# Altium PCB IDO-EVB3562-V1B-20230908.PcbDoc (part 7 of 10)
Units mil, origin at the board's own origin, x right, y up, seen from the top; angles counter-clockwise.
Board outline 5314.96 x 3543.31 mil, 4 copper layers (TOP, L2-VCC, L3-GND, BOTTOM), stack 28.8 mil thick; 747 components, 560 nets, 2514 pads, 1964 vias.
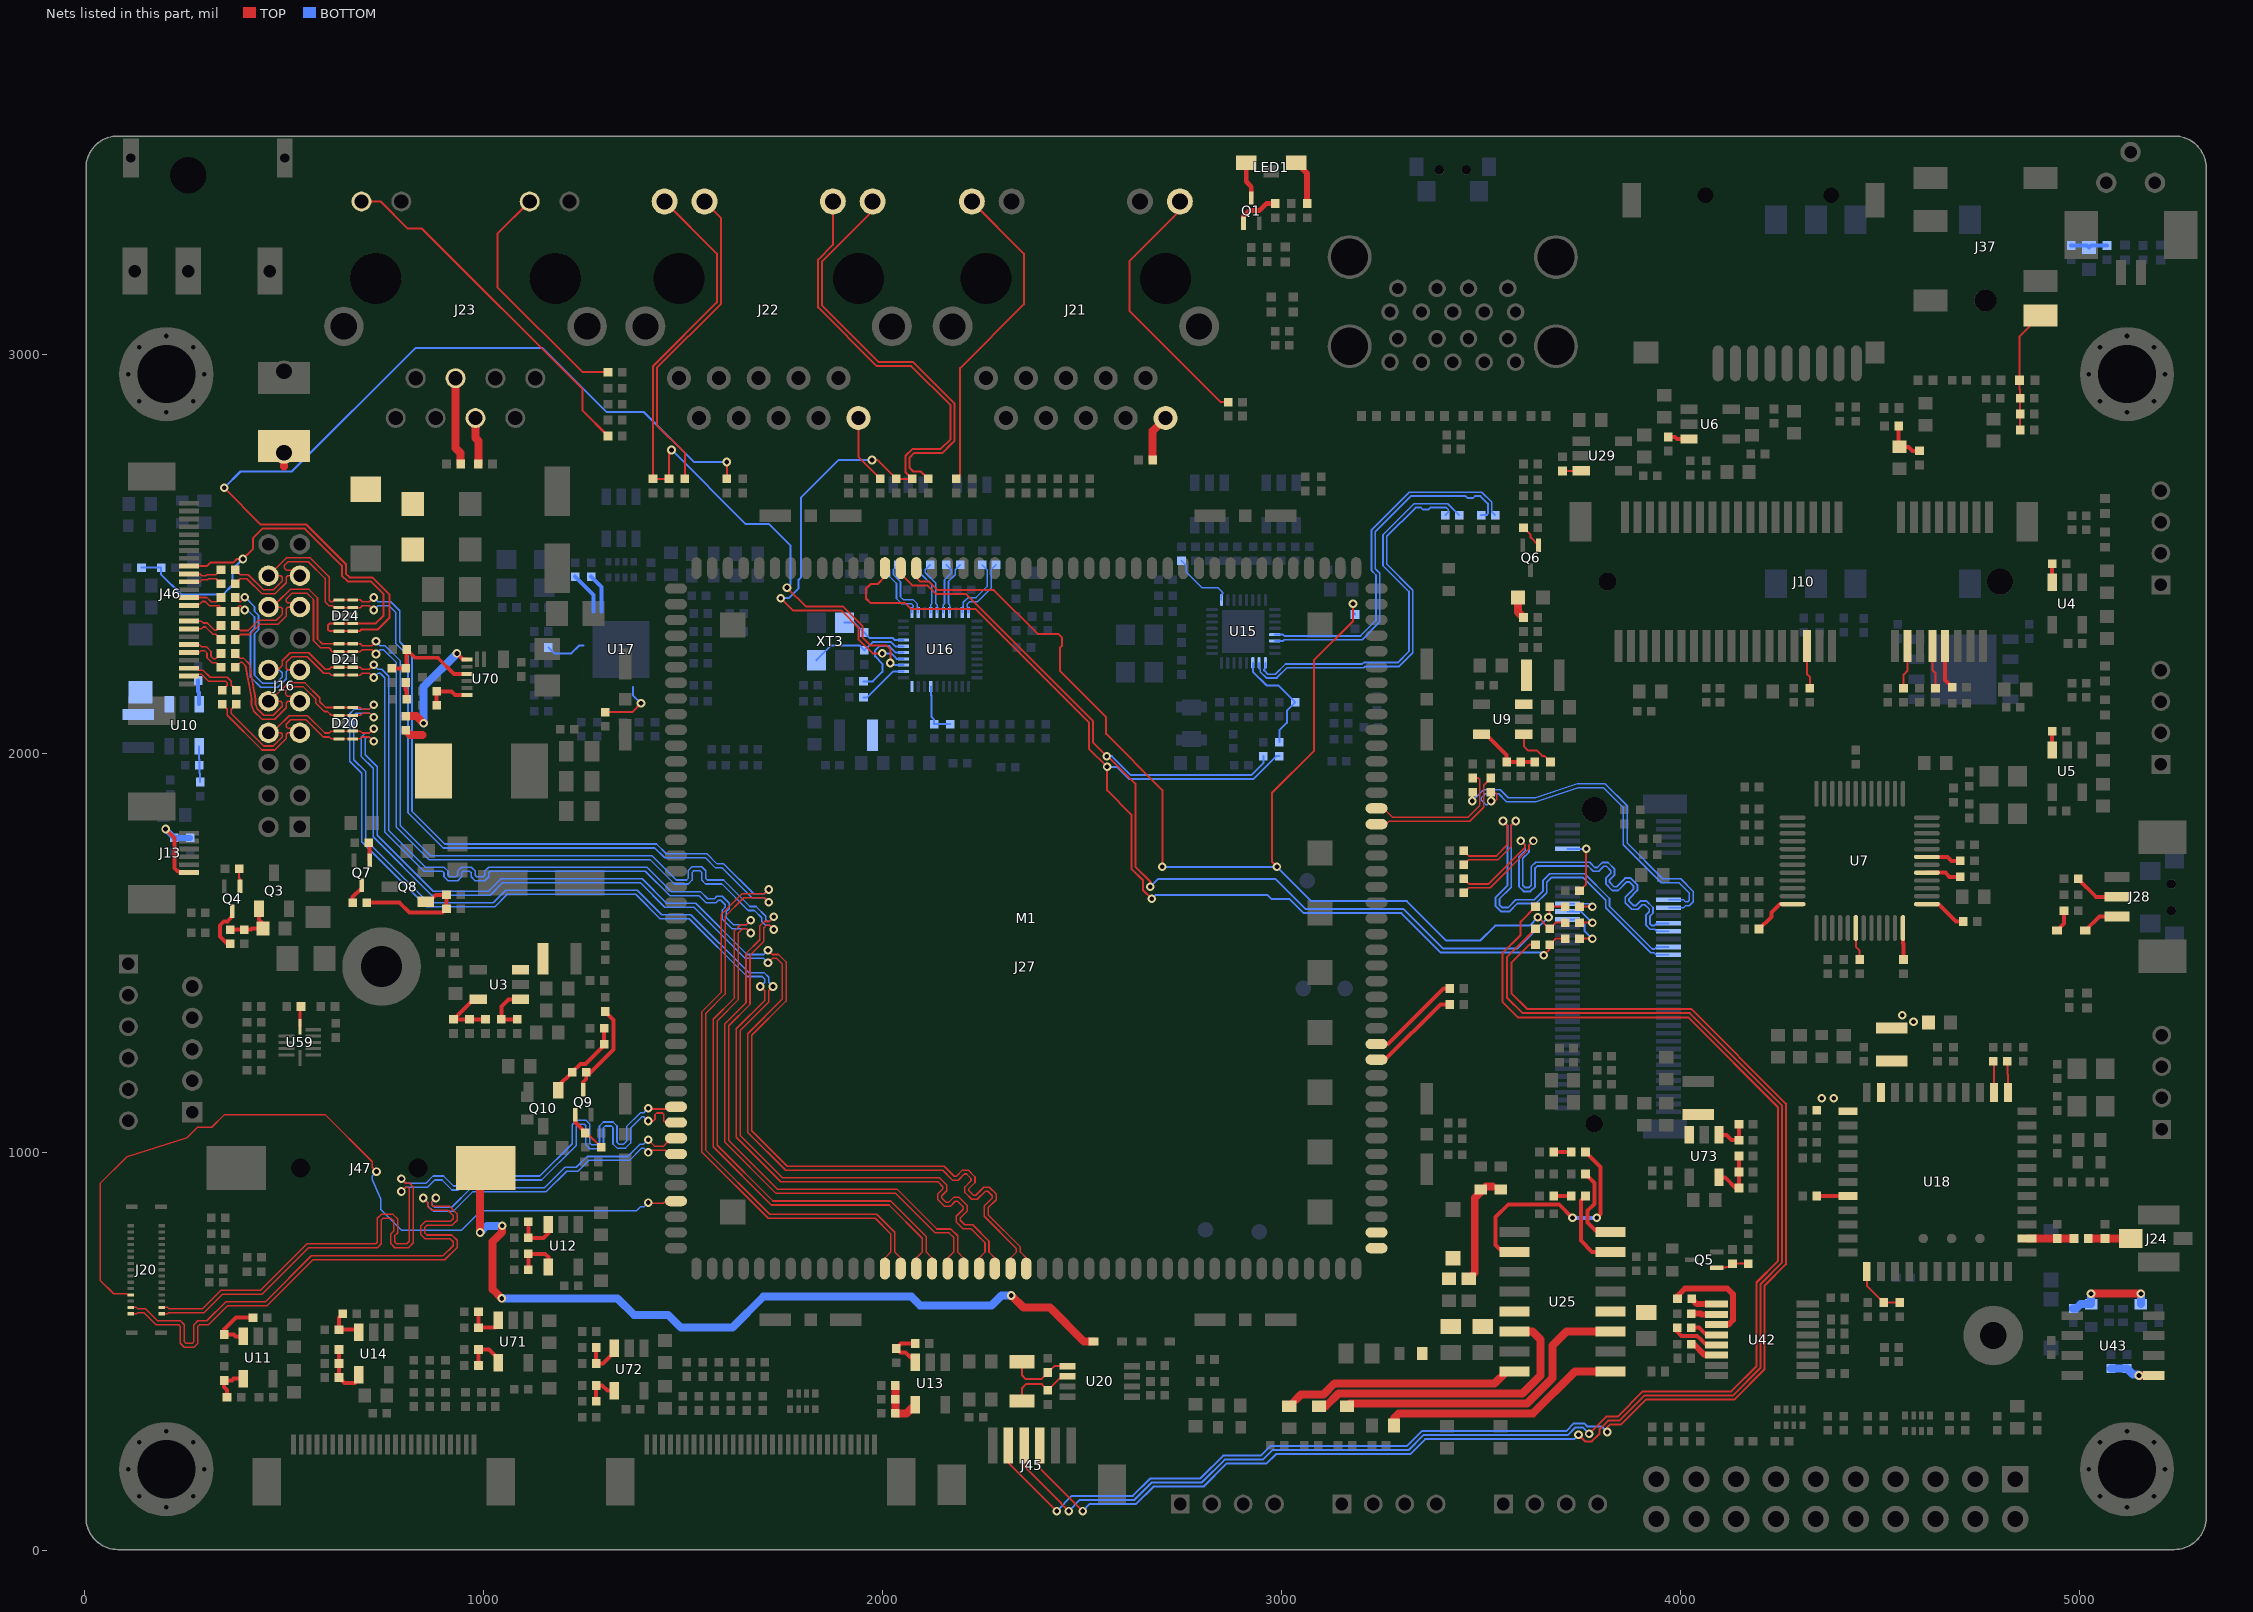
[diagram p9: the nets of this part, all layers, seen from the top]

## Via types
v1: diameter 21.65, hole 11.81, TOP to BOTTOM, 1964 vias

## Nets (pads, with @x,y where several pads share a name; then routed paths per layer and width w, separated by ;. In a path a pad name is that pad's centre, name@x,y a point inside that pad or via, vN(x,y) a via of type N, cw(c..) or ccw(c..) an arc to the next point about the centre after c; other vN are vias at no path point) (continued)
MIPI_CSI_RX1_D1P: J20.7 M1.126 | length 2051.3
  TOP w4: J20.7@116.03,642 108,642 105.12,644.88 72.98,644.88 39,678.86 39,921.14 106.22,988.37 256.79,1035.94 283.03,1062.17 318.8,1062.17 350.63,1094 603,1094 721.2,975.8 721.2,961.88 v1(732.03,951.05) ; v1(1413,873.31) 1414.31,872 1451.01,872 1456.17,877.16 M1.126@1482.87,877.16
  BOTTOM w4: v1(732.03,951.05) 721.2,940.23 721.2,931.01 742.52,882.01 742.52,856.25 794.77,804 944.9,804 993.9,853 1383.86,853 1393.34,862.48 1402.17,862.48 v1(1413,873.31)
MIPI_CSI_RX1_D2N: J20.3 M1.123 | length 2039.2
  TOP w4: J20.3@116.03,610.51 130.13,610.51 133,607.63 152.51,607.63 183.14,577 240.39,577 250.25,567.14 250.25,525 254.25,521 270.25,521 274.25,525 274.25,567.14 284.11,577 306.49,577 354.44,624.96 453.5,624.96 568.54,740 898.86,740 924,765.14 924,774.86 916.65,782.21 854.2,782.21 843.35,793.06 843.35,815.35 854.2,826.21 917.06,826.21 924,833.14 924,840.86 910.86,854 870,854 860,864 860,874.17 v1(849.17,885) ; v1(1413,999.13) 1418.87,1005 1456,1005 1465.72,995.28 M1.123@1482.87,995.28
  BOTTOM w4: v1(849.17,885) 860,874.17 860,865.86 873.86,852 925.01,852 974.01,901 1157.61,901 1208.79,952.17 1237.13,952.17 1263.96,979 1366.14,979 1397.1,1009.96 1402.17,1009.96 v1(1413,999.13)
MIPI_CSI_RX1_D2P: J20.1 M1.122 | length 2049.7
  TOP w4: J20.1@116.03,594.76 130.13,594.76 133,597.63 148.37,597.63 179,567 236.25,567 240.25,563 240.25,520.86 250.11,511 274.39,511 284.25,520.86 284.25,563 288.25,567 310.63,567 358.58,614.96 457.64,614.96 572.68,730 903,730 934,761 934,779 920.79,792.21 858.35,792.21 853.35,797.21 853.35,811.21 858.35,816.21 921.21,816.21 934,829 934,845 915,864 874.14,864 870,868.14 870,874.17 v1(880.83,885) ; v1(1413,1030.79) 1428.79,1015 1452,1015 1459,1022 1459,1026 1467.64,1034.65 M1.122@1482.87,1034.65
  BOTTOM w4: v1(880.83,885) 870,874.17 870,870 878,862 920.87,862 969.87,911 1153.47,911 1204.64,962.17 1232.99,962.17 1259.82,989 1362,989 1392.96,1019.96 1402.17,1019.96 v1(1413,1030.79)
MIPI_CSI_RX1_D3N: J20.4 M1.121 | length 2040.2
  TOP w4: J20.4@193.98,610.51 208.08,610.51 210.95,607.63 296.11,607.63 342.43,653.96 441.48,653.96 557.53,770 730.06,770 734.06,774 734.06,833.8 743.92,843.66 773.34,843.66 785,832 785,798 778.06,791.06 778.06,774 782.06,770 807.86,770 814.35,776.49 814.35,908.54 810.83,912.05 805.17,912.05 v1(794.35,901.23) ; v1(1413,1077.87) 1425.87,1077.87 1430,1082 1430,1094 1434,1098 1449,1098 1452,1095 1452,1078 1455.98,1074.02 M1.121@1482.87,1074.02
  BOTTOM w4: v1(794.35,901.23) 805.17,912.05 859.91,912.05 877.86,930 896,930 921,905 937,905 962,930 1145.6,930 1232.32,1016.72 1232.32,1064.01 1237.99,1069.67 1252.85,1069.67 1256.85,1065.67 1256.85,1017.86 1266.7,1008 1290.99,1008 1300.85,1017.86 1300.85,1061.44 1304.85,1065.44 1320.85,1065.44 1324.85,1061.44 1324.85,1020.15 1335,1010 1356.13,1010 1368.85,1022.72 1368.85,1059.85 1397.7,1088.7 1402.17,1088.7 v1(1413,1077.87)
MIPI_CSI_RX1_D3P: J20.2 M1.120 | length 2040.9
  TOP w4: J20.2@193.98,594.76 208.08,594.76 210.95,597.63 300.25,597.63 346.57,643.96 445.62,643.96 561.67,760 734.2,760 744.06,769.86 744.06,829.66 748.06,833.66 769.2,833.66 775,827.86 775,802.14 768.06,795.2 768.06,769.86 777.92,760 812,760 824.35,772.35 824.35,912.68 814.97,922.05 805.17,922.05 v1(794.35,932.88) ; v1(1413,1109.53) 1414.53,1108 1458,1108 1463.39,1113.39 M1.120@1482.87,1113.39
  BOTTOM w4: v1(794.35,932.88) 805.17,922.05 855.77,922.05 873.72,940 900.14,940 925.14,915 932.86,915 957.86,940 1141.46,940 1222.32,1020.87 1222.32,1068.15 1233.85,1079.67 1256.99,1079.67 1266.85,1069.82 1266.85,1022 1270.85,1018 1286.85,1018 1290.85,1022 1290.85,1065.58 1300.7,1075.44 1324.99,1075.44 1334.85,1065.58 1334.85,1024.3 1339.14,1020 1351.99,1020 1358.85,1026.86 1358.85,1063.99 1393.56,1098.7 1402.17,1098.7 v1(1413,1109.53)
MIPI_DSI_RST: C93.2 D24.4 D24.5 D24.6 D24.7 J46.16 R78.1 R444.1 | length 3524.9
  TOP w5: J46.16@262.01,2468.9 306.9,2468.9 316.35,2478.35 373.67,2478.35 382,2486.68 v1(397,2486.68) 422,2511.68 422,2539 445.75,2562.75 552.25,2562.75 645,2470 645,2445 659.52,2430.48 717.62,2430.48 750,2398.11 750,2345 730.32,2325.32 D24.7@672.22,2325.32 D24.4@637.78,2325.32 615.32,2325.32 610,2320 610,2310 614.37,2305.63 D24.5@637.78,2305.63 D24.6@672.22,2305.63 690,2305.63 694.37,2310 735,2310 765,2340 765,2397.25 721.77,2440.48 664.52,2440.48 655,2450 655,2474.14 556.39,2572.75 442.25,2572.75 v1(350,2665) ; R78.1@1610,2687.72 v1(1610,2730)
  BOTTOM w5: C93.2@142.72,2465 R444.1@192.28,2465 192.28,2447.72 241.78,2398.22 347.73,2398.22 371,2421.49 371,2460.68 v1(397,2486.68) ; v1(350,2665) 391,2706 520,2706 829.5,3015.5 1148.55,3015.5 1309.05,2855 1402.54,2855 1527.54,2730 v1(1610,2730)
MIPI_DSI_TX_CLKN/LVDS_TX_CLKN: D21.4 D21.7 J16.15 M1.147 R1186.1 | length 3564.1
  TOP w4: R1186.1@377.72,2285 390.22,2297.5 414.64,2297.5 440.14,2323 476.68,2323 476.71,2322.96 485,2322.96 505.63,2343.59 505.63,2362.18 509.63,2366.18 J16.15@540,2366.18 529.18,2377 509,2377 505.63,2380.37 505.63,2386.32 519.71,2400.39 558.61,2400.39 574,2385 574,2281.86 591.49,2264.37 613.25,2264.37 617.25,2260.37 617.25,2257.76 620.32,2254.68 D21.7@637.78,2254.68 D21.4@672.22,2254.68 691.43,2254.68 696.28,2259.53 719.94,2259.53 v1(730.76,2248.7) ; v1(1727.83,1557.96) 1717.71,1568.08 1708.5,1568.08 1702.83,1562.4 1702.83,1528.04 1668.18,1493.4 1668.18,1370.18 1614.82,1316.82 1614.82,1029.24 1737.67,906.39 2037.75,906.39 2136.89,807.25 2171.39,807.25 2188.66,789.98 2188.66,749.26 2203.35,734.58 M1.147@2203.35,707.87
  BOTTOM w4: v1(730.76,2248.7) 741.59,2259.53 749.33,2259.53 781.83,2227.03 781.83,1814.19 862.84,1733.17 1417.7,1733.17 1478.87,1672 1513.14,1672 1522.99,1681.86 1522.99,1701 1526.99,1705 1542.99,1705 1546.99,1701 1546.99,1681.86 1556.85,1672 1597.75,1672 1664.09,1605.65 1679.35,1605.65 1697.83,1587.17 1697.83,1578.16 1707.2,1568.79 1717,1568.79 v1(1727.83,1557.96)
MIPI_DSI_TX_CLKP/LVDS_TX_CLKP: D21.5 D21.6 J16.16 M1.146 R1187.1 | length 3569.8
  TOP w4: R1187.1@377.72,2320 390.22,2307.5 410.5,2307.5 436,2333 480.82,2333 480.86,2332.96 495.63,2347.73 495.63,2362.18 491.63,2366.18 J16.16@461.26,2366.18 473.08,2378 483.17,2378 515.57,2410.39 562.75,2410.39 584,2389.14 584,2286 595.63,2274.37 D21.6@637.78,2274.37 D21.5@672.22,2274.37 691.44,2274.37 696.28,2269.53 719.94,2269.53 v1(730.76,2280.35) ; v1(1727.83,1589.61) 1716.29,1578.08 1704.36,1578.08 1692.83,1566.55 1692.83,1532.18 1658.18,1497.54 1658.18,1374.33 1604.82,1320.96 1604.82,1025.1 1733.53,896.39 2033.61,896.39 2132.75,797.25 2167.25,797.25 2178.66,785.84 2178.66,749.26 2163.98,734.58 M1.146@2163.98,707.87
  BOTTOM w4: v1(730.76,2280.35) 741.59,2269.53 753.48,2269.53 791.83,2231.17 791.83,1818.33 866.98,1743.17 1421.84,1743.17 1483.01,1682 1508.99,1682 1512.99,1686 1512.99,1705.14 1522.85,1715 1547.14,1715 1556.99,1705.14 1556.99,1686 1560.99,1682 1601.89,1682 1668.24,1615.65 1683.49,1615.65 1707.83,1591.31 1707.83,1582.3 1711.35,1578.79 1717,1578.79 v1(1727.83,1589.61)
MIPI_DSI_TX_D0N/LVDS_TX_D0N: D20.1 D20.10 J16.7 M1.151 R1182.1 | length 3487.9
  TOP w4: R1182.1@345,2122.28 357.5,2109.78 357.5,2095.36 444.86,2008 477.14,2008 505.63,2036.49 505.63,2047.22 509.63,2051.22 J16.7@540,2051.22 529.22,2062 510,2062 505.63,2066.37 505.63,2072.47 517.16,2084 555,2084 598.52,2040.47 613.72,2040.47 618.57,2035.63 D20.10@637.78,2035.63 D20.1@672.22,2035.63 691.43,2035.63 696.28,2040.47 713.94,2040.47 v1(724.76,2029.65) ; v1(1713.27,1506.2) 1724.1,1495.37 1739.63,1495.37 1758.65,1476.35 1758.65,1378.62 1672.82,1292.79 1672.82,1053.27 1761.7,964.39 2155.49,964.39 2180.23,939.64 2185.89,939.64 2201.15,954.91 2208.12,954.91 2215.09,954.91 2232.27,937.73 2232.27,923.79 2217.01,908.53 2217.01,902.87 2228.32,891.56 2233.98,891.56 2254.24,911.82 2268.18,911.82 2285.36,894.64 2285.36,887.67 2285.35,880.7 2265.09,860.44 2265.09,843.05 2346.14,762 2346.14,749.26 2360.83,734.58 M1.151@2360.83,707.87
  BOTTOM w4: v1(724.76,2029.65) 713.94,2040.47 708.28,2040.47 704,2036.19 704,1995.79 733.83,1965.96 733.83,1794.3 874.13,1654 1012.62,1654 1043.8,1685.17 1397.81,1685.17 1458.98,1624 1531.95,1624 1660.58,1495.37 1702.44,1495.37 v1(1713.27,1506.2)
MIPI_DSI_TX_D0P/LVDS_TX_D0P: D20.2 D20.9 J16.8 M1.150 R1183.1 | length 3481.9
  TOP w4: R1183.1@380,2122.28 367.5,2109.78 367.5,2099.5 449,2018 473,2018 495.63,2040.63 495.63,2047.22 491.63,2051.22 J16.8@461.26,2051.22 473.04,2063 482.01,2063 513.01,2094 559.14,2094 602.67,2050.47 613.72,2050.47 618.56,2055.32 D20.9@637.78,2055.32 D20.2@672.22,2055.32 691.44,2055.32 696.28,2050.47 713.94,2050.47 v1(724.76,2061.3) ; v1(1713.27,1474.55) 1724.1,1485.37 1735.48,1485.37 1748.65,1472.2 1748.65,1382.77 1662.82,1296.94 1662.82,1049.12 1757.56,954.39 2151.34,954.39 2176.09,929.64 2190.03,929.64 2205.29,944.91 2208.12,944.91 2210.95,944.91 2222.27,933.59 2222.27,930.76 2222.27,927.93 2207.01,912.67 2207.01,898.73 2224.18,881.56 2238.12,881.56 2258.38,901.82 2264.04,901.82 2275.36,890.5 2275.36,884.85 2255.09,864.58 2255.09,838.91 2336.14,757.86 2336.14,749.26 2321.46,734.58 M1.150@2321.46,707.87
  BOTTOM w4: v1(724.76,2061.3) 713.94,2050.47 704.14,2050.47 694,2040.34 694,1991.64 723.83,1961.82 723.83,1790.16 869.99,1644 1016.77,1644 1047.94,1675.17 1393.67,1675.17 1454.84,1614 1527.81,1614 1656.44,1485.37 1702.44,1485.37 v1(1713.27,1474.55)
MIPI_DSI_TX_D1N/LVDS_TX_D1N: D20.4 D20.7 J16.9 M1.149 R1184.1 | length 3517
  TOP w4: R1184.1@377.72,2215 390.22,2227.5 395.36,2227.5 403.59,2219.26 418.67,2135.82 418.67,2119.86 424.5,2105.36 444.86,2085 477.14,2085 505.63,2113.49 505.63,2125.96 509.63,2129.96 J16.9@540,2129.96 526.96,2143 508,2143 504,2147 504,2155.11 515,2166.11 548.75,2166.11 580,2134.86 580,2125 600.63,2104.37 608.88,2104.37 618.57,2094.68 D20.7@637.78,2094.68 D20.4@672.22,2094.68 691.43,2094.68 697.28,2100.53 714.17,2100.53 v1(725,2089.7) ; v1(1725.83,1415) 1715,1404.17 1715,1375.98 1643.82,1304.81 1643.82,1041.25 1749.69,935.39 2143.47,935.39 2161.57,917.29 2161.57,903.35 2149.01,890.79 2149.01,887.96 2149.01,885.13 2160.34,873.81 2165.99,873.81 2178.55,886.37 2192.49,886.37 2212.66,866.2 2212.66,852.26 2195.1,834.7 2195.11,829.04 2206.42,817.72 2216.22,817.72 2226.42,817.72 2267.4,776.74 2267.4,749.26 2282.09,734.58 M1.149@2282.09,707.87
  BOTTOM w4: v1(725,2089.7) 714.17,2100.53 680.67,2100.53 675,2094.86 675,1983.77 704.83,1953.95 704.83,1782.29 862.12,1625 1024.64,1625 1055.81,1656.17 1385.8,1656.17 1446.97,1595 1519.94,1595 1664.94,1450 1703.13,1450 1715,1438.13 1715,1425.83 v1(1725.83,1415)
MIPI_DSI_TX_D1P/LVDS_TX_D1P: D20.5 D20.6 J16.10 M1.148 R1185.1 | length 3518.4
  TOP w4: R1185.1@377.72,2250 390.22,2237.5 399.5,2237.5 412.88,2224.12 428.67,2136.72 428.67,2121.8 433.02,2110.98 449,2095 473,2095 495.63,2117.63 495.63,2125.96 491.63,2129.96 J16.10@461.26,2129.96 474.3,2143 477.75,2143 510.86,2176.11 552.89,2176.11 590,2139 590,2129.14 604.77,2114.37 D20.6@637.78,2114.37 D20.5@672.22,2114.37 691.44,2114.37 695.28,2110.53 714.17,2110.53 v1(725,2121.35) ; v1(1694.17,1415) 1705,1404.17 1705,1380.13 1633.82,1308.95 1633.82,1037.11 1745.54,925.39 2139.33,925.39 2151.57,913.14 2151.57,907.49 2139.01,894.93 2139.01,887.96 2139.01,880.99 2156.19,863.81 2170.13,863.81 2182.69,876.37 2188.35,876.37 2202.66,862.05 2202.66,856.4 2185.1,838.84 2185.1,824.9 2202.28,807.72 2216.22,807.72 2222.28,807.72 2257.4,772.6 2257.4,749.26 2242.72,734.58 M1.148@2242.72,707.87
  BOTTOM w4: v1(725,2121.35) 714.17,2110.53 676.53,2110.53 665,2099 665,1979.63 694.83,1949.8 694.83,1778.14 857.97,1615 1028.78,1615 1059.95,1646.17 1381.65,1646.17 1442.83,1585 1515.8,1585 1660.8,1440 1698.98,1440 1705,1433.98 1705,1425.83 v1(1694.17,1415)
MIPI_DSI_TX_D2N/LVDS_TX_D2N: D21.1 D21.10 J16.11 M1.145 R1188.1 | length 3535.3
  TOP w4: R1188.1@377.72,2355 377.72,2360.36 387.17,2369.81 391.17,2369.81 v1(402,2358.98) ; J16.11@540,2208.7 509.63,2208.7 505.63,2212.7 505.63,2227.63 520,2242 558,2242 599.52,2200.47 613.72,2200.47 618.57,2195.63 D21.10@637.78,2195.63 D21.1@672.22,2195.63 691.43,2195.63 696.28,2200.47 713.94,2200.47 v1(724.76,2189.65) ; v1(1670,1549.17) 1659.17,1560 1649.14,1560 1639.18,1550.04 1639.18,1382.2 1585.82,1328.84 1585.82,1017.23 1725.66,877.39 2020.75,877.39 2109.92,788.22 2109.92,749.26 2124.61,734.58 M1.145@2124.61,707.87
  BOTTOM w4: v1(402,2358.98) 408.46,2358.98 426,2341.44 426,2313.14 416,2303.14 416,2191 442,2165 484.14,2165 505.63,2186.49 505.63,2204.7 509.63,2208.7 J16.11@540,2208.7 ; v1(724.76,2189.65) 735.59,2200.47 741.25,2200.47 752.83,2188.9 752.83,1802.17 850.83,1704.17 897.2,1704.17 901.2,1700.17 901.2,1689.86 911.05,1680 935.34,1680 945.2,1689.86 945.2,1700.17 949.2,1704.17 965.2,1704.17 969.2,1700.17 969.2,1689.86 979.05,1680 1003.34,1680 1013.2,1689.86 1013.2,1700.17 1017.2,1704.17 1405.68,1704.17 1466.86,1643 1539.83,1643 1557.83,1625 1583.13,1625 1589.17,1631.04 1594.82,1631.04 1606.14,1619.72 1606.14,1614.06 1599,1606.92 1599,1583.83 1622.83,1560 1659.17,1560 v1(1670,1549.17)
MIPI_DSI_TX_D2P/LVDS_TX_D2P: D21.2 D21.9 J16.12 M1.144 R1189.1 | length 3556.6
  TOP w4: R1189.1@377.72,2390 387.91,2379.81 391.17,2379.81 v1(402,2390.64) ; J16.12@461.26,2208.7 484.7,2208.7 495.63,2219.63 495.63,2231.77 515.86,2252 562.14,2252 603.67,2210.47 613.72,2210.47 618.56,2215.32 D21.9@637.78,2215.32 D21.2@672.22,2215.32 691.44,2215.32 696.28,2210.47 713.94,2210.47 v1(724.76,2221.3) ; v1(1670,1580.83) 1659.17,1570 1645,1570 1629.18,1554.18 1629.18,1386.34 1575.82,1332.98 1575.82,1013.08 1721.52,867.39 2016.61,867.39 2099.92,784.08 2099.92,749.26 2085.24,734.58 M1.144@2085.24,707.87
  BOTTOM w4: v1(402,2390.64) 402.63,2390.64 426,2367.26 426,2355.59 436,2345.59 436,2309 426,2299 426,2195.14 446.14,2175 480,2175 495.63,2190.63 495.63,2201.37 488.3,2208.7 J16.12@461.26,2208.7 ; v1(724.76,2221.3) 735.59,2210.47 745.39,2210.47 762.83,2193.04 762.83,1806.32 854.97,1714.17 901.34,1714.17 911.2,1704.32 911.2,1694 915.2,1690 931.2,1690 935.2,1694 935.2,1704.32 945.05,1714.17 969.34,1714.17 979.2,1704.32 979.2,1694 983.2,1690 999.2,1690 1003.2,1694 1003.2,1704.32 1013.05,1714.17 1409.83,1714.17 1471,1653 1543.97,1653 1561.97,1635 1578.99,1635 1585.02,1641.04 1598.96,1641.04 1616.14,1623.86 1616.14,1609.92 1609,1602.78 1609,1587.97 1626.97,1570 1659.17,1570 v1(1670,1580.83)
MIPI_DSI_TX_D3N/LVDS_TX_D3N: D24.2 D24.9 J16.17 M1.143 R1190.1 | length 3553.5
  TOP w4: R1190.1@377.72,2425 390.22,2437.5 406.5,2437.5 444,2400 478.3,2400 505.63,2427.33 505.63,2440.92 509.63,2444.92 J16.17@540,2444.92 526.92,2458 507,2458 501,2464 501,2470.52 510.18,2479.7 561.15,2479.7 603,2437.86 603,2379.38 612.86,2369.53 621.47,2369.53 626.32,2364.68 D24.2@637.78,2364.68 D24.9@672.22,2364.68 691.43,2364.68 696.28,2369.53 713.94,2369.53 v1(724.76,2358.7) ; v1(1715,1626.46) 1704.17,1637.29 1652.29,1637.29 1605.79,1590.79 1605.79,1396.03 1556.82,1347.06 1556.82,1005.21 1718.04,844 1986.12,844 2031.18,798.93 2031.18,749.26 2045.87,734.58 M1.143@2045.87,707.87
  BOTTOM w4: v1(724.76,2358.7) 735.59,2369.53 763.33,2369.53 780,2352.86 780,2275 810.83,2244.17 810.83,1850.38 899.04,1762.17 1429.71,1762.17 1454.28,1737.61 1556.39,1737.61 1581.62,1712.38 1598.38,1712.38 1673.47,1637.29 1704.17,1637.29 v1(1715,1626.46)
MIPI_DSI_TX_D3P/LVDS_TX_D3P: D24.1 D24.10 J16.18 M1.142 R1191.1 | length 3554.5
  TOP w4: R1191.1@377.72,2460 390.22,2447.5 410.64,2447.5 448.14,2410 474.16,2410 495.63,2431.47 495.63,2440.92 491.63,2444.92 J16.18@461.26,2444.92 506.04,2489.7 565.3,2489.7 613,2442 613,2383.53 617,2379.53 622.53,2379.53 627.37,2384.37 D24.1@637.78,2384.37 D24.10@672.22,2384.37 691.44,2384.37 696.28,2379.53 713.94,2379.53 v1(724.76,2390.35) ; v1(1715,1658.12) 1704.17,1647.29 1648.15,1647.29 1595.79,1594.94 1595.79,1400.17 1546.82,1351.2 1546.82,1001.07 1713.89,834 1981.97,834 2021.18,794.79 2021.18,749.26 2006.5,734.58 M1.142@2006.5,707.87
  BOTTOM w4: v1(724.76,2390.35) 735.59,2379.53 767.47,2379.53 790,2357 790,2279.14 820.83,2248.32 820.83,1854.53 903.18,1772.17 1433.85,1772.17 1458.42,1747.61 1560.54,1747.61 1585.76,1722.38 1602.53,1722.38 1677.62,1647.29 1704.17,1647.29 v1(1715,1658.12)
MIPI_TX_BL_PWM: R75.2 R82.2 U10.4 | length 90.2
  BOTTOM w5: U10.4@287.4,2016.85 287.4,1985 287.72,1984.68 R82.2@287.72,1970 287.72,1950 290,1947.72 R75.2@290,1927.72
MIPI_TX_CLKN: J46.8 R1186.2 | length 95.2
  TOP w4: J46.8@262.01,2311.42 292.84,2311.42 297.68,2316.26 303.52,2316.26 321.78,2298 329.28,2298 R1186.2@342.28,2285
MIPI_TX_CLKP: J46.9 R1187.2 | length 94.8
  TOP w4: J46.9@262.01,2331.1 292.84,2331.1 297.68,2326.26 307.66,2326.26 325.92,2308 330.28,2308 R1187.2@342.28,2320
MIPI_TX_D0N: J46.2 R1182.2 | length 130.1
  TOP w4: J46.2@262.01,2193.31 283.31,2193.31 288.15,2198.15 292.71,2198.15 310.86,2180 353.5,2180 357.5,2176 357.5,2170.22 R1182.2@345,2157.72
MIPI_TX_D0P: J46.3 R1183.2 | length 146.7
  TOP w4: J46.3@262.01,2212.99 282.01,2212.99 286.85,2208.15 296.85,2208.15 315,2190 357.64,2190 367.5,2180.14 367.5,2170.22 R1183.2@380,2157.72
MIPI_TX_D1N: J46.5 R1184.2 | length 106.8
  TOP w4: J46.5@262.01,2252.36 287.36,2252.36 292.2,2257.2 300.65,2257.2 307,2250.86 307,2238.86 318.86,2227 330.28,2227 R1184.2@342.28,2215
MIPI_TX_D1P: J46.6 R1185.2 | length 107.2
  TOP w4: J46.6@262.01,2272.05 287.95,2272.05 292.8,2267.2 304.8,2267.2 317,2255 317,2243 323,2237 329.28,2237 R1185.2@342.28,2250
MIPI_TX_D2N: J46.11 R1188.2 | length 100.4
  TOP w4: J46.11@262.01,2370.47 285.47,2370.47 295.16,2380.16 302.7,2380.16 313.36,2369.5 337.5,2369.5 342.28,2364.72 R1188.2@342.28,2355
MIPI_TX_D2P: J46.12 R1189.2 | length 89
  TOP w4: J46.12@262.01,2390.16 306.84,2390.16 317.5,2379.5 331.78,2379.5 R1189.2@342.28,2390
MIPI_TX_D3N: J46.14 R1190.2 | length 88.3
  TOP w4: J46.14@262.01,2429.53 289.53,2429.53 294.37,2434.37 308.37,2434.37 311,2437 330.28,2437 R1190.2@342.28,2425
MIPI_TX_D3P: J46.15 R1191.2 | length 88.9
  TOP w4: J46.15@262.01,2449.21 262.19,2449.4 288.6,2449.4 293.63,2444.37 304.23,2444.37 306.86,2447 329.28,2447 R1191.2@342.28,2460
N19354508: C1048.1 R136.1 R137.2 U13.4 | length 128.9
  TOP w20: R137.2@2032.72,415 R136.1@2032.72,380 C1048.1@2032.72,344.99 2060.74,344.99 U13.4@2082.6,366.85
N19356461: R132.1 R133.2 U11.4 | length 94.8
  TOP w10: R132.1@357.28,385 357.28,404 350,411.28 R133.2@350,427.28 369.43,427.28 374,431.85 U11.4@397.6,431.85
N19357233: R134.1 R135.2 U12.4 | length 118
  TOP w10: R134.1@1112.72,705 R135.2@1112.72,745 1154,745 1162.6,736.4 U12.4@1162.6,711.85
N19411583: J21.14 R157.1 | length 819.8
  TOP w5: R157.1@2185,2687.72 2195,2697.72 2195,2965 2355,3125 2355,3252.1 J21.14@2224.2,3382.9
N19487510: C84.1 Q3.1 R80.1 R443.2 | length 137.2
  TOP w10: R443.2@365,1557.72 R80.1@400,1557.72 417.72,1557.72 420,1560 C84.1@447.44,1560 447.44,1572.56 437.6,1582.4 Q3.1@437.6,1609.72
N19487520: Q4.3 R443.1 | length 113.3
  TOP w10: R443.1@365,1522.28 357.72,1522.28 340,1540 340,1568.57 350.01,1578.57 358.57,1578.57 370,1590 Q4.3@370,1603.5
N20425490: J21.11 R150.1 | length 669.6
  TOP w5: J21.11@2745.8,3382.9 2745.8,3359.8 2619,3233 2619,3109 2848,2880 R150.1@2867.28,2880
N69227900: L3.1 U3.3
N69227918: C31.1 R8.1 R10.2 U3.5 | length 162.5
  TOP w10: U3.5@986.85,1382.6 974.88,1382.6 C31.1@925,1332.72 R8.1@965,1332.72 R10.2@1005,1332.72
N69724413: C37.2 R9.2 U3.1 | length 127.7
  TOP w10: R9.2@1085,1332.72 C37.2@1045,1332.72 1045,1365 1062.6,1382.6 U3.1@1093.15,1382.6
N69763264: C1049.1 M1.14 | length 241.1
  TOP w10: M1.14@3238.78,1270.87 3267.87,1270.87 3407.01,1410.01 C1049.1@3422.28,1410.01
N69763270: C1050.1 M1.13 | length 240.9
  TOP w10: M1.13@3238.78,1231.5 3260.5,1231.5 3399.01,1370.01 C1050.1@3422.28,1370.01
N69764395: J10.10 R54.1 | length 108.9
  TOP w5: J10.10@4632.8,2268.6 4632.8,2207.2 4640,2200 R54.1@4640,2162.72
N69764397: J10.14 R56.1 | length 109.9
  TOP w5: R56.1@4560,2162.72 4560,2197 4569.8,2206.8 J10.14@4569.8,2268.6
N69764433: LED2.A R452.1 | length 55.7
  TOP w20: LED2.A@3593.5,2390 3593.5,2353.78 R452.1@3607.28,2340
N69764492: R441.2 U9.1 | length 113.8
  TOP w5: U9.1@3608.15,2047.6 3608.15,2016.85 3618,2007 3640,2007 3654,1993 3659.72,1993 R441.2@3675,1977.72
N69764501: C79.1 R60.1 R442.2 U9.5 | length 172.2
  TOP w10: U9.5@3501.85,2047.6 3512.4,2047.6 3565,1995 C79.1@3565,1977.72 R60.1@3600,1977.72 R442.2@3635,1977.72
N69764515: L7.1 U9.3
N69764582: J10.8 R52.1 | length 111
  TOP w10: J10.8@4664.3,2268.6 4664.3,2182.98 R52.1@4682.28,2165
N69765778: R31.1 U4.3 | length 47
  TOP w10: R31.1@4932.28,2475 4932.6,2474.68 U4.3@4932.6,2428.15
N69765789: R34.1 U5.3 | length 47
  TOP w10: R34.1@4932.28,2055 4932.28,2008.47 U5.3@4932.6,2008.15
N69765908: R439.1 U7.48 | length 79.7
  TOP w10: U7.48@4558.3,1561.7 4558.3,1522.7 4560,1521 R439.1@4560,1482.72
N69765931: R438.1 U7.36 | length 116.2
  TOP w10: R438.1@4197.72,1559 4228.5,1589.78 4228.5,1600.5 4249.7,1621.7 U7.36@4281.7,1621.7
N69765961: R435.2 U7.5 | length 88.3
  TOP w10: U7.5@4618.3,1700.5 4664.5,1700.5 4675,1690 R435.2@4702.28,1690
N69765963: R436.2 U7.7 | length 88
  TOP w10: U7.7@4618.3,1739.8 4670.2,1739.8 4680,1730 R436.2@4702.28,1730
N69774873: R244.2 U18.29 | length 78
  TOP w10: R244.2@4342.72,890 4372,890 4372.43,889.57 U18.29@4420.59,889.57
N69774879: R245.2 R246.2 U18.34 | length 135.3
  TOP w5: U18.34@4467.83,700.59 4467.83,664.89 R245.2@4510,622.72 R246.2@4550,622.72
N69774884: C168.2 R225.1 U18.2 | length 117.9
  TOP w20: U18.2@4869.41,783.27 C168.2@4945,783.27 R225.1@4987.28,783.27
N69774885: C169.2 J24.2 R225.2 | length 106.4
  TOP w20: R225.2@5022.72,783.27 C169.2@5065,783.27 J24.2@5129.13,783.27
N69774891: C343.2 C367.2 L13.2 U18.23
  other v1: 4355,1135 4385,1135 4585,1327 4557,1343
N69774914: L13.1 U18.21
N69774994: R238.2 U18.12 | length 78.8
  TOP w5: R238.2@4820,1227.28 4820,1196 4822.17,1193.83 U18.12@4822.17,1149.41
N69783431: D43.C J28.1 | length 94.6
  TOP w10: D43.C@5015.43,1555 5015.43,1555.43 5050.79,1590.79 J28.1@5095,1590.79
N69783435: J28.2 R464.2 | length 115.9
  TOP w10: R464.2@4997.72,1685 5042.72,1640 J28.2@5095,1640
N69783454: D43.A R463.2 | length 57.3
  TOP w10: D43.A@4944.57,1555 4962.28,1572.71 R463.2@4962.28,1605
N69784782: C189.2 U20.1 XT6.1 | length 165.1
  TOP w5: XT6.1@2350,474.21 2350,441 2360,431 2398.72,431 C189.2@2415,447.28 2431.11,463.39 U20.1@2464.29,463.39
N69784786: C191.2 U20.2 XT6.2 | length 171.5
  TOP w5: XT6.2@2350,375.79 2350,408 2360,418 2399.72,418 C191.2@2415,402.72 2450.08,437.8 U20.2@2464.29,437.8
N69784848: D49.A J47.1 | length 2044.5
  TOP w20: v1(991.56,798.33) 991.56,945.58 J47.1@1005.98,960 ; v1(1046,633.17) 1023.17,656 1023.17,775.99 1047,799.82 v1(1047,815.1) ; v1(2323,640.56) 2353.48,610.08 2419.92,610.08 2505,525 D49.A@2529.57,525
  BOTTOM w20: v1(991.56,798.33) 1008.32,815.1 v1(1047,815.1) ; v1(1046,633.17) 1336.25,633.17 1377.42,592 1463,592 1494.83,560.17 1624.17,560.17 1701.4,637.4 2072.7,637.4 2094.76,615.35 2273.39,615.35 2298.6,640.56 v1(2323,640.56)
N69791555: R434.2 U7.1 | length 109.1
  TOP w10: U7.1@4618.3,1621.7 4647.3,1621.7 4691,1578 R434.2@4709.28,1578
N69811283: D18.A L8.2 U10.1
N69811295: R84.1 U10.3 | length 60.1
  BOTTOM w10: R84.1@285,2182.28 285,2155 287.4,2152.6 U10.3@287.4,2123.15
N69814289: LED1.1 R19.2 | length 113.5
  TOP w15: LED1.1@3037.99,3480 3065,3452.99 R19.2@3065,3377.72
N69814308: LED1.2 Q1.3 | length 93.9
  TOP w12: LED1.2@2912.01,3480 2912.01,3432.99 2925,3420 Q1.3@2925,3391.5
N69814328: Q1.1 R21.2 | length 109.9
  TOP w12: Q1.1@2905.32,3328.5 2905.32,3345.32 2920,3360 2945,3360 2962.72,3377.72 R21.2@2985,3377.72
N69841804: D1.A D2.A D3.C F3.2 F4.2 | length 103.7
  TOP w20: F4.2@465.44,2753 F3.2@500,2753 ; 500,2718.44 F3.2@500,2753 ; F4.2@534.56,2753 F3.2@500,2753
N69861791: C82.2 J13.1 R62.2 | length 219.8
  TOP w10: v1(203.21,1810) 225.83,1787.38 225.83,1711.51 232.87,1704.47 234.39,1704.47 238.08,1700.79 J13.1@262.01,1700.79
  BOTTOM w15: v1(203.21,1810) 203.21,1809.52 C82.2@225.01,1787.72 R62.2@265,1787.72
N69863607: C281.2 R388.1 R465.2 | length 94.3
  BOTTOM w10: R465.2@4980,3272.72 5019.84,3272.72 C281.2@5025,3267.56 5030.16,3272.72 R388.1@5070,3272.72
N69863700: C280.2 R387.1 R466.2 | length 107.5
  TOP w10: R387.1@4547.72,2820 4547.72,2769.84 C280.2@4550,2767.56 4572.44,2767.56 4582.28,2757.72 R466.2@4600,2757.72
N69865878: C223.2 D67.1 J37.5 R314.1 R455.2 | length 309.4
  TOP w5: R455.2@4852.28,2810 R314.1@4852.28,2850 C223.2@4852.28,2890 4852.28,2910.72 4851.1,2911.9 D67.1@4851.1,2935 4851.1,3044.95 J37.5@4903.39,3097.24
N69867903: L26.1 U25.1 | length 608.6
  TOP w20: L26.1@3282.56,315 3282.56,332.56 3294.48,344.48 3630.48,344.48 3736,450 U25.1@3825,450
N69867905: L25.1 U25.3 | length 785.4
  TOP w20: L25.1@3165,362.56 3171.92,369.48 3616.05,369.48 3680,433.43 3680,515 3715,550 U25.3@3825,550
N69867925: L27.1 U25.14 | length 750.4
  TOP w20: L27.1@3095,362.56 3111.31,362.56 3143.23,394.48 3604.48,394.48 3650,440 3650,530 3630,550 U25.14@3585,550
N69867927: L28.1 U25.16 | length 601.2
  TOP w20: L28.1@3020,362.56 3049.76,392.32 3105.71,392.32 3132.87,419.48 3534.48,419.48 3565,450 U25.16@3585,450
N69867929: C215.2 R303.1 | length 44.6
  TOP w10: C215.2@3682.72,890.01 3703.57,890.01 ; 3703.58,890 R303.1@3727.28,890
N69867931: R303.2 U25.7 | length 202.5
  TOP w10: R303.2@3762.72,890 3751,878.28 3751,778 3779,750 U25.7@3825,750
N69867938: C219.2 R309.1 | length 44.6
  TOP w10: C219.2@3682.72,1000.01 3706.86,1000 R309.1@3727.28,1000
N69867940: R309.2 U25.10 | length 589.6
  TOP w10: U25.10@3585,750 3555,750 3537.5,767.5 3537.5,837.5 3569.15,869.15 3696.02,869.15 v1(3730.17,835) ; R309.2@3762.72,1000 3800,962.72 3800,844.17 v1(3790.83,835)
  BOTTOM w10: v1(3730.17,835) v1(3790.83,835)
N69867965: C214.2 U25.8 | length 204.9
  TOP w10: C214.2@3762.72,945.01 3785,922.73 3785,870 3767.93,852.93 3767.93,823.07 3791,800 U25.8@3825,800
N69871260: Q5.1 R446.1 R454.2 | length 83.6
  TOP w5: Q5.1@4091.5,710.32 4113.31,710.32 4115.28,712.28 4123,712.28 R446.1@4131,720.28 R454.2@4171,720.28
N69917404: C369.1 R138.1 R139.2 U14.4 | length 140.9
  TOP w10: R139.2@637.72,505 R138.1@637.72,470 C369.1@637.72,435 651.72,421 678,421 687.6,430.6 U14.4@687.6,441.85
N69923813: C114.2 J21.1 | length 118.4
  TOP w20: C114.2@2677.72,2735.01 2677.72,2807.72 J21.1@2710,2840
N69957333: C147.2 J22.1 | length 175.1
  TOP w5: J22.1@1940,2840 1940,2742.71 C147.2@1994.99,2687.72
N69957443: J22.11 R189.1 | length 1054.4
  TOP w5: J22.11@1975.8,3382.9 1975.8,3359.8 1849,3233 1849,3121.57 1990.57,2980 2077,2980 2181,2876 2181,2783.26 2173.37,2775.63 2149.74,2752 2079.14,2752 2068,2740.86 2068,2716 2077.93,2706.07 2096.65,2706.07 R189.1@2115,2687.72
N69960536: J22.13 R193.1 | length 807.3
  TOP w5: R193.1@1505,2687.72 1505,2752.54 1435,2822.54 1435,2965.86 1595,3125.86 1595,3342.1 J22.13@1554.2,3382.9
N69961030: C163.2 J23.4 | length 118
  TOP w20: J23.4@980,2840 980,2790 987.28,2782.72 C163.2@987.28,2725
N69961588: C166.2 J23.5 | length 220.3
  TOP w20: J23.5@930,2940 930,2765 942.72,2752.28 C166.2@942.72,2725
N69966336: J23.12 R219.2 | length 893.1
  TOP w5: J23.12@694.17,3382.91 742.09,3382.91 810,3315 845.96,3315 1247.98,2912.98 1247.98,2859.3 R219.2@1312.28,2795
N70024964: R341.1 U29.3 | length 47
  TOP w5: R341.1@3705,2707.28 3705.32,2707.6 U29.3@3751.85,2707.6
N70036634: Q6.1 R456.2 | length 59
  TOP w5: R456.2@3607.28,2565 3625,2547.28 3625,2541.18 Q6.1@3644.68,2521.5
N70058734: R35.1 U6.3 | length 54
  TOP w10: R35.1@3970,2792.72 3987.28,2792.72 3992.4,2787.6 U6.3@4021.85,2787.6
N70074623: C265.2 R130.2 U11.3 | length 146.6
  TOP w10: U11.3@397.6,538.15 378.85,538.15 374.28,542.72 C265.2@349.99,542.72 349.99,555.21 379.78,585 R130.2@422.28,585
N70074833: C266.2 R373.2 U12.3 | length 116.2
  TOP w10: R373.2@1112.72,825 C266.2@1112.72,785 1151,785 1162.6,796.6 U12.3@1162.6,818.15
N70075015: C267.2 R374.2 U13.3 | length 114.3
  TOP w10: R374.2@2082.28,520 2047.27,520 C267.2@2034.99,507.72 2044.71,498 2057.75,498 U13.3@2082.6,473.15
N70075198: C268.2 R375.2 U14.3 | length 96.7
  TOP w10: R375.2@647.28,595 637.72,585.44 C268.2@637.72,555 680.75,555 U14.3@687.6,548.15
N70088511: R448.1 U59.12 | length 51.8
  TOP w8: U59.12@540,1314.37 540,1362.28 R448.1@542.72,1365
N70100637: R414.1 U7.42 | length 83
  TOP w5: U7.42@4440.2,1561.7 4440.2,1514.8 4450,1505 R414.1@4450,1482.72
N70130938: C339.2 U17.29 | length 102.2
  BOTTOM w5: C339.2@1162.72,2265 1177.72,2250 1220.24,2250 1240.09,2269.85 U17.29@1250.5,2269.85
N70140073: Q4.1 R453.2 | length 44.3
  TOP w5: R453.2@387.72,1710 387.72,1687.28 389.69,1685.32 Q4.1@389.69,1666.5
N70164941: R787.2 R1060.1 R1061.2 U70.9 | length 259.8
  TOP w10: R787.2@770,2212.72 R1061.2@805,2212.72 807.72,2215.44 R1060.1@807.72,2260 828.57,2239.15 885.49,2239.15 925.78,2198.86 U70.9@958.82,2198.86
N70165129: R782.2 R783.2 U70.12 | length 114.9
  TOP w10: R783.2@882.72,2120 R782.2@882.72,2155 920,2155 929.29,2145.71 U70.12@958.82,2145.71
N70165139: C810.1 U70.7 | length 293.8
  TOP w10: v1(933.46,2250) 949.17,2234.29 U70.7@958.82,2234.29
  TOP w20: C810.1@805.01,2092.72 832.28,2092.72 v1(850,2075)
  BOTTOM w20: v1(850,2075) 850,2166.54 v1(933.46,2250)
N70165141: C810.2 L33.1 U70.2 | length 46.8
  TOP w20: C810.2@805.01,2057.28 817.29,2045 846.72,2045
N70165164: C815.2 R1061.1 | length 43.4
  TOP w10: R1061.1@805,2177.28 805,2160 807.72,2157.28 C815.2@807.72,2135.01
N70166760: C1012.1 Q8.1 R1062.2 R1063.1 | length 308.3
  TOP w10: R1062.2@707.72,1625 790,1625 815,1600 897.28,1600 R1063.1@907.28,1610 C1012.1@907.28,1645.01 881.01,1645.01 863.6,1627.6 Q8.1@855.28,1627.6
N70166762: Q7.3 R1062.1 | length 52.9
  TOP w10: R1062.1@672.28,1625 672.28,1639.28 695,1662 Q7.3@695,1668.5
N70166881: Q7.1 R4.2 | length 44.3
  TOP w10: R4.2@712.72,1775 714.68,1773.04 Q7.1@714.68,1731.5
N70177512: R1066.1 R1067.2 U71.4 | length 109.2
  TOP w10: R1066.1@987.72,465 R1067.2@987.72,505 1014,505 1037.6,481.4 U71.4@1037.6,471.85
N70177574: C1014.2 R1065.2 U71.3 | length 103.6
  TOP w10: R1065.2@987.72,600 C1014.2@987.72,560 1030,560 1037.6,567.6 U71.3@1037.6,578.15
N70177973: R1069.1 R1070.2 U72.4 | length 90.3
  TOP w10: R1069.1@1282.72,375 R1070.2@1282.72,415 1297.72,415 1310.87,401.85 U72.4@1327.6,401.85
N70178035: C1018.2 R1068.2 U72.3 | length 106.9
  TOP w10: R1068.2@1282.72,510 C1018.2@1282.72,470 1300,470 1327.6,497.6 U72.3@1327.6,508.15
N70190247: C1034.1 Q10.1 R1079.2 R1080.1 | length 210.2
  TOP w10: Q10.1@1187.4,1155.28 1187.4,1165.12 R1079.2@1222.28,1200 1222.28,1200.4 1242.73,1220.85 1255.85,1220.85 1302.72,1267.72 R1080.1@1302.72,1270 C1034.1@1302.72,1309.99
N70190249: Q9.3 R1079.1 R1083.2 | length 242.1
  TOP w10: Q9.3@1250,1156.5 1250,1175 1257.72,1182.72 R1079.1@1257.72,1200 1268.57,1200 1325.73,1257.17 1325.73,1331.55 R1083.2@1305,1352.28
N70190329: Q9.1 R1078.2 R1192.1 | length 110.7
  TOP w5: R1078.2@1255,1047.72 1259.56,1047.72 R1192.1@1295,1012.28
  TOP w10: Q9.1@1230.32,1093.5 1230.32,1074.43 1255,1049.75 R1078.2@1255,1047.72
N70208813: C282.2 C283.2 D79.A M1.1 M1.2 R1209.1 R1210.1 | length 265.5
  TOP w20: C282.2@3470,682.56 3485,697.56 3485,885 3513.66,913.66 3530,913.66
N70209347: C1035.2 J10.22 | length 108.8
  TOP w5: J10.22@4317.9,2268.6 4317.9,2198.1 4325,2191 C1035.2@4325,2162.72
N70209679: C529.1 U42.1 | length 68.1
  TOP w15: C529.1@4028.72,632 4041.98,618.74 U42.1@4091.3,618.74
N70209681: C529.2 U42.3 | length 270.4
  TOP w15: C529.2@3993.28,632 3993.28,639.07 4012.21,658 4118,658 4132.35,643.65 4132.35,578.89 4121,567.54 U42.3@4091.3,567.54
N70209685: C527.1 U42.4 | length 71.1
  TOP w10: C527.1@4027.72,559.99 4047.3,559.99 4065.36,541.94 U42.4@4091.3,541.94
N70209687: C527.2 U42.5 | length 122.5
  TOP w10: C527.2@3992.28,559.99 3992.28,550.72 4003.86,539.14 4042.42,539.14 4050.4,531.16 4050.53,531.16 4065.36,516.34 U42.5@4091.3,516.34
N70209691: C530.1 U42.2 | length 64.4
  TOP w15: C530.1@4027.72,595 4051,595 4052.86,593.14 U42.2@4091.3,593.14
N70209695: C528.1 U42.6 | length 74.9
  TOP w15: C528.1@4027.72,518 4034.56,518 4061.82,490.74 U42.6@4091.3,490.74
N70210897: C1039.1 R1169.2 R1170.1 U73.5 | length 141
  TOP w10: U73.5@4097.4,936.85 4112.15,936.85 4139,910 C1039.1@4147.28,910 R1170.1@4147.28,950 R1169.2@4147.28,990
N70210968: L44.1 U73.3
N70211090: C1045.2 R1171.2 U73.1 | length 95.3
  TOP w10: U73.1@4097.4,1043.15 4115.85,1043.15 4129,1030 C1045.2@4147.28,1030 R1171.2@4147.28,1070
N70266506: J23.10 R218.2 | length 613.7
  TOP w5: J23.10@1115.83,3382.91 1035,3302.09 1035,3168.39 1248.39,2955 R218.2@1312.28,2955
N70266836: R1200.1 U17.19 | length 148.2
  TOP w5: R1200.1@1305,2102.72 1372.72,2102.72 v1(1395,2125)
  BOTTOM w5: U17.19@1374.55,2165.5 1374.55,2145.45 v1(1395,2125)
N70310222: C533.1 R461.2 R462.2 | length 227.4
  TOP w20: v1(5030,645) v1(5155,645)
  BOTTOM w20: C533.1@4984.99,607.72 4992.72,607.72 5003.54,618.54 R461.2@5030,618.54 v1(5030,645) ; R462.2@5155,618.54 v1(5155,645)
N70310339: C531.1 R460.1 U43.5 | length 114.5
  TOP w20: v1(5150,440) U43.5@5187.36,440
  BOTTOM w20: R460.1@5080,457.28 C531.1@5120.01,457.28 5135.01,442.28 5147.72,442.28 v1(5150,440)
N70379039: R1211.2 U18.13 | length 78.6
  TOP w5: R1211.2@4785,1227.28 4786.73,1225.55 U18.13@4786.73,1149.41
N76747942: R209.1 U17.1 | length 106.9
  BOTTOM w10: R209.1@1230,2442.28 1276.05,2396.23 U17.1@1276.05,2354.5
N76750177: C341.2 U17.2 | length 98.4
  BOTTOM w10: C341.2@1270,2442.28 1295.75,2416.53 U17.2@1295.75,2354.5
PA_5V: C210.2 C211.2 C212.2 R300.1 U25.4 U25.13
PCIE20_0_TXN: C317.2 U15.14 | length 889.4
  BOTTOM w4.5: U15.14@2983.74,2281.38 3004.67,2281.38 3007.8,2284.51 3202.62,2284.51 3247,2328.89 3247,2450.55 3235.5,2462.05 3235.5,2555.28 3324.72,2644.5 3462.06,2644.5 3467.06,2639.5 3480.56,2639.5 3485.56,2644.5 3499.06,2644.5 3517.91,2625.66 3517.91,2599.91 3514.72,2596.72 C317.2@3501.01,2596.72
PCIE20_0_TXP: C319.2 U15.13 | length 889.5
  BOTTOM w4.5: U15.13@2983.74,2297.13 3004.67,2297.13 3007.8,2294.01 3198.68,2294.01 3237.5,2332.82 3237.5,2446.62 3226,2458.12 3226,2559.22 3320.78,2654 3503,2654 3527.41,2629.59 3527.41,2605.32 C319.2@3536.01,2596.72
PCIE20_32KHZ: J27.68 R342.2 | length 159.5
  TOP w5: R342.2@3747.72,1655 3764.41,1671.69 v1(3764.41,1760.28)
  BOTTOM w5: J27.68@3717.09,1760.28 v1(3764.41,1760.28)
PCIE20_CLKREQN: J27.52 R258.2 | length 106.7
  TOP w5: R258.2@3747.72,1575 v1(3780,1575)
  BOTTOM w5: J27.52@3717.09,1602.8 3752.2,1602.8 v1(3780,1575)
PCIE20_CLKREQN_M1: M1.72 R155.1 R258.1 R308.1 | length 3040.5
  TOP w5: M1.72@2085.24,2463.78 2085.24,2439.76 2095,2430 2117.48,2430 2138.76,2408.72 2279.52,2408.72 2389.24,2299 2441,2299 2450,2290 2450,2269 2445.67,2264.67 2445.67,2205.46 2561,2090.13 2561,2048.17 2701.67,1907.5 v1(2701.67,1715) ; v1(2989.06,1715) 2989.06,1715.94 2976.65,1728.35 2976.65,1900.12 3081.64,2005.11 3081.64,2233.03 3179.93,2331.33 v1(3179.93,2374.4) ; v1(3643.1,1588.32) 3643.84,1588.32 3672.16,1560 R308.1@3672.72,1560 3687.72,1575 R258.1@3712.28,1575
  BOTTOM w5: v1(2701.67,1715) v1(2989.06,1715) 3075.06,1629 3314.78,1629 3413.84,1529.94 3498.16,1529.94 3535.87,1567.65 3622.43,1567.65 v1(3643.1,1588.32) ; v1(3179.93,2374.4) 3179.93,2352.79 R155.1@3185,2347.72
PCIE20_PERSTN: J27.50 R260.2 | length 123.9
  TOP w5: R260.2@3747.72,1535 v1(3780,1535)
  BOTTOM w5: J27.50@3717.09,1583.11 3746.89,1583.11 3760,1570 3760,1555 v1(3780,1535)
PCIE20_PERSTN_M1: M1.74 R153.1 R260.1 R311.1 | length 2896.8
  TOP w5: M1.74@2006.5,2463.78 2006.5,2442.5 1988,2424 1971,2424 1959,2412 1959,2387.67 1970,2376.67 2056.36,2376.67 2071.36,2361.67 2232.89,2361.67 2517.5,2077.06 2517.5,2011.55 v1(2563.34,1965.71) 2563.34,1906.66 2624.31,1845.69 2624.31,1710.69 2653.35,1681.65 2653.35,1656.65 v1(2675,1635) ; v1(3657.72,1493.32) 3672.72,1508.32 R311.1@3672.72,1520 3687.72,1535 R260.1@3712.28,1535
  BOTTOM w5: v1(2563.34,1965.71) 2587.77,1965.71 2618.68,1934.8 2929.83,1934.8 2987.31,1992.28 R153.1@2995,1992.28 ; v1(2675,1635) 2685,1645 2965,1645 2975,1635 3020,1635 3056,1599 3301.01,1599 3400.06,1499.94 3651.1,1499.94 v1(3657.72,1493.32)
PCIE20_REFCLKN: M1.29 R404.1 R408.1 | length 365.1
  TOP w4: M1.29@3238.78,1861.42 3256.58,1861.42 3279,1839 3468,1839 3497.5,1868.5 3497.5,1934.5 3494.28,1937.72 R408.1@3480,1937.72
PCIE20_REFCLKN_: J27.53 R408.2 | length 862.4
  TOP w4: v1(3479,1880) 3480,1881 R408.2@3480,1902.28
  BOTTOM w4: v1(3479,1880) 3507,1908 3549,1908 3568.89,1888.11 3636.95,1888.11 3741.95,1923.2 3811.72,1923.2 3867,1867.91 3867,1774.63 3956.63,1685 4001.14,1685 4032.85,1653.29 4032.85,1627.34 4022.99,1617.48 4013.19,1617.48 4008.35,1612.64 J27.53@3971.02,1612.64
PCIE20_REFCLKP: M1.28 R403.1 R407.1 | length 366.4
  TOP w4: M1.28@3238.78,1822.05 3263.05,1822.05 3270,1829 3472.14,1829 3507.5,1864.36 3507.5,1919.78 R403.1@3525,1937.28
PCIE20_REFCLKP_: J27.55 R407.2 | length 862.2
  TOP w4: R407.2@3525,1902.28 3535.72,1902.28 3540.55,1897.45 3540.55,1884.55 3536,1880 v1(3526,1880)
  BOTTOM w4: v1(3526,1880) 3517,1871 3512.6,1871 3501.75,1881.85 3501.75,1888.61 3511.14,1898 3544.86,1898 3564.75,1878.11 3638.57,1878.11 3743.57,1913.2 3807.57,1913.2 3857,1863.77 3857,1770.48 3952.48,1675 3997,1675 4022.85,1649.15 4022.85,1631.48 4018.85,1627.48 4013.19,1627.48 4008.35,1632.32 J27.55@3971.02,1632.32
PCIE20_RXDN: J27.41 R406.2 | length 1001.8
  TOP w4.5: R406.2@3457.72,1755 3470.47,1742.25 3539.3,1742.25 3567,1769.95 3567,1818.93 v1(3555.92,1830.01)
  BOTTOM w4.5: v1(3555.92,1830.01) 3567,1818.93 3567,1668 3537.4,1638.4 3537.4,1616.4 3550.4,1603.4 3572.4,1603.4 3592,1623 3638,1623 3665.34,1650.34 3665.34,1676.14 3677.2,1688.01 3756.97,1688.01 3813.25,1631.73 3813.25,1612.31 3925.94,1499.62 3934.38,1499.62 3939.47,1494.53 J27.41@3971.02,1494.53
PCIE20_RXDP: J27.43 R405.2 | length 1001.8
  TOP w4.5: R405.2@3457.72,1720 3470.47,1732.75 3543.24,1732.75 3576.5,1766.01 3576.5,1818.93 v1(3587.58,1830.01)
  BOTTOM w4.5: v1(3587.58,1830.01) 3576.5,1818.93 3576.5,1664.06 3546.9,1634.47 3546.9,1620.34 3554.34,1612.9 3568.47,1612.9 3588.06,1632.5 3634.06,1632.5 3655.84,1654.28 3655.84,1680.08 3673.27,1697.51 3760.91,1697.51 3822.75,1635.66 3822.75,1616.25 3929.88,1509.12 3936.12,1509.12 3941.21,1514.21 J27.43@3971.02,1514.21
PCIE20_TXDN: C354.1 J27.47 | length 1008
  TOP w4.5: C354.1@3457.72,1685 3470.47,1672.25 3519.81,1672.25 3611.5,1763.94 3611.5,1768.92 v1(3600.42,1780)
  BOTTOM w4.5: v1(3600.42,1780) 3611.5,1768.92 3611.5,1756 3596,1740.5 3596,1665 3607.5,1653.5 3624.5,1653.5 3636.34,1665.34 3636.34,1711.9 3641.44,1717.01 3768.99,1717.01 3782.1,1703.89 3796.34,1703.89 3808.83,1716.38 3815.19,1716.38 3826.16,1705.41 3826.16,1699.05 3813.67,1686.56 3813.67,1672.32 3830.19,1655.8 3844.43,1655.8 3865.92,1677.29 3872.28,1677.29 3883.24,1666.32 3883.24,1659.96 3862.34,1639.06 3862.34,1625.23 3878.87,1608.71 3893.52,1608.71 3905.01,1620.2 3911.36,1620.2 3922.33,1609.23 3922.33,1602.87 3914.5,1595.04 3914.5,1568.5 3924.32,1558.68 3936.32,1558.68 3941.42,1553.58 J27.47@3971.02,1553.58
PCIE20_TXDP: C353.1 J27.49 | length 1008
  TOP w4.5: C353.1@3457.72,1650 3470.47,1662.75 3523.75,1662.75 3621,1760 3621,1768.92 v1(3632.08,1780)
  BOTTOM w4.5: v1(3632.08,1780) 3621,1768.92 3621,1752.06 3605.5,1736.56 3605.5,1668.94 3611.44,1663 3620.56,1663 3626.84,1669.28 3626.84,1715.84 3637.51,1726.51 3772.92,1726.51 3786.04,1713.39 3792.4,1713.39 3804.89,1725.88 3819.12,1725.88 3835.66,1709.34 3835.66,1695.11 3823.17,1682.62 3823.17,1676.26 3834.13,1665.3 3840.49,1665.3 3861.98,1686.79 3876.21,1686.79 3892.74,1670.25 3892.74,1656.02 3871.84,1635.12 3871.84,1629.17 3882.8,1618.21 3889.58,1618.21 3901.07,1629.7 3915.3,1629.7 3931.83,1613.16 3931.83,1598.93 3924,1591.1 3924,1572.43 3928.26,1568.18 3936.18,1568.18 3941.27,1573.27 J27.49@3971.02,1573.27
PCIE20_WAKEN: J27.54 R259.2 | length 98.3
  TOP w5: R259.2@3747.72,1615 v1(3780,1615)
  BOTTOM w5: J27.54@3717.09,1622.48 3772.52,1622.48 v1(3780,1615)
PCIE20_WAKEN_M1: M1.73 R154.1 R259.1 R310.1 | length 2746.8
  TOP w5: M1.73@2045.87,2463.78 2045.87,2449.99 2075.86,2420 2113.34,2420 2134.61,2398.72 2209.98,2398.72 2527.5,2081.2 2527.5,2027.46 v1(2562.45,1992.52) 2565.49,1992.52 2634.31,1923.69 2634.31,1879.08 ; 2634.31,1879.07 2634.31,1854.22 2634.31,1715.69 2671.67,1678.33 v1(2671.67,1665) ; v1(3669.76,1588.32) 3672.72,1591.29 R310.1@3672.72,1615 R259.1@3712.28,1615
  BOTTOM w5: v1(2562.45,1992.52) 2575.1,1992.52 2622.82,1944.8 2924.83,1944.8 2955,1974.97 R154.1@2955,1992.28 ; v1(2671.67,1665) 2691.67,1685 2985,1685 3061,1609 3306.49,1609 3405.55,1509.94 3591.37,1509.94 v1(3669.76,1588.32)
PCIE_0_RXN: R402.2 U15.18 | length 964.5
  BOTTOM w4.5: U15.18@2944.37,2226.26 2944.37,2213.63 2947.49,2210.51 2947.49,2203.51 2962.5,2188.5 2988.94,2188.5 3014.44,2214 3207,2214 3210.5,2217.5 3295.49,2217.5 3329.74,2251.75 3329.74,2408.82 3264.5,2474.07 3264.5,2543.27 3336.73,2615.5 3350.23,2615.5 3355.23,2610.5 3368.73,2610.5 3373.73,2615.5 3413.78,2615.5 3418.6,2610.68 3418.6,2604.32 R402.2@3411,2596.72
PCIE_0_RXP: R401.2 U15.17 | length 964.6
  BOTTOM w4.5: U15.17@2960.12,2226.26 2960.12,2213.12 2956.99,2209.99 2956.99,2207.44 2966.44,2198 2985,2198 3010.5,2223.5 3203.06,2223.5 3206.56,2227 3291.55,2227 3320.24,2255.69 3320.24,2404.89 3255,2470.13 3255,2547.2 3332.8,2625 3417.72,2625 R401.2@3446,2596.72
PDM_CLK0_M0: J45.3 R308.2 | length 3760.7
  TOP w5: J45.3@2394.68,264.33 2394.68,207.55 v1(2502.24,100) ; R308.2@3637.28,1560 3565.55,1488.28 3565.55,1387.45 3605,1348 4024.14,1348 4255,1117.14 4255,722.54 4201.35,668.89 4201.35,459.15 4132.49,390.3 3910.76,390.3 3847.12,326.65 3819.35,326.65 3798.33,305.63 3798.33,294.51 3778.82,275 3761.44,275 v1(3745.12,291.32)
  BOTTOM w5: v1(2502.24,100) 2520.13,117.89 2636.18,117.89 2679.96,161.67 2805.29,161.67 2862.45,218.84 2962.84,218.84 2986.84,242.84 3323.12,242.84 3360.61,280.33 3734.12,280.33 v1(3745.12,291.32)
PDM_SDI1_M0: J45.5 R311.2 | length 3807.3
  TOP w5: J45.5@2315.95,264.33 2315.95,221.29 v1(2437.24,100) ; R311.2@3637.28,1520 3622,1520 3577,1475 3577,1398 3616,1359 4027.29,1359 4265,1121.29 4265,718.4 4211.35,664.75 4211.35,455.01 4136.64,380.3 3914.91,380.3 3851.26,316.65 3823.5,316.65 3816.95,310.1 v1(3816.95,298.33)
  BOTTOM w5: v1(2437.24,100) 2475.13,137.89 2627.89,137.89 2671.67,181.67 2797,181.67 2854.16,238.84 2948.84,238.84 2972.84,262.84 3314.84,262.84 3352.33,300.33 3714.06,300.33 3733.38,319.65 3759.92,319.65 3767.48,312.09 3803.18,312.09 v1(3816.95,298.33)
PDM_SDI2_M0: J45.4 R310.2 | length 3843.2
  TOP w5: J45.4@2355.32,264.33 2355.32,212.92 2447.24,121 2447.24,120 v1(2467.24,100) ; R310.2@3637.28,1615 3600,1577.72 3600,1544.17 3554,1498.17 3554,1377.04 3594.04,1337 4021,1337 4245,1113 4245,726.69 4191.35,673.03 4191.35,463.29 4128.35,400.3 3906.62,400.3 3842.98,336.65 3814.55,336.65 v1(3771.66,293.76)
  BOTTOM w5: v1(2467.24,100) 2495.13,127.89 2632.04,127.89 2675.82,171.67 2801.14,171.67 2858.31,228.84 2953.84,228.84 2977.84,252.84 3318.98,252.84 3356.47,290.33 3718.2,290.33 3737.53,309.65 3755.77,309.65 v1(3771.66,293.76)
PERSTB: C318.2 R153.2 U15.19 | length 276.6
  BOTTOM w5: U15.19@2928.62,2226.26 2928.62,2204.38 2963,2170 2992.72,2170 C318.2@3035,2127.72 3014,2106.72 3014,2076 2995,2057 R153.2@2995,2027.72
PHY0_CLKOUT125: R170.2 U16.35 | length 200.4
  BOTTOM w5: R170.2@1952.72,2180 1976,2180 2000.01,2204 2000.01,2224.07 1981.67,2242.41 1981.67,2257.59 1992.41,2268.33 2017.8,2268.33 2033.99,2252.13 U16.35@2052.48,2252.13
PHY0_LED0/CFG_EXT: R174.2 U16.32 | length 126.6
  BOTTOM w5: R174.2@1952.72,2140 1962,2140 2026.88,2204.88 U16.32@2052.48,2204.88
PHY0_LED1/CFG_LDO0: C133.2 J22.14 R176.2 U16.33 | length 1845.5
  TOP w5: J22.14@1454.2,3382.9 1585,3252.1 1585,3130 1425,2970 C133.2@1425,2687.72 R176.2@1465,2687.72 1465,2753.48 v1(1471.57,2760.05) ; v1(1760.87,2414.99) 1808.79,2367.07 1901.82,2367.07 1950,2318.89 1950,2290 1970,2270 2010,2270 2020,2260 v1(2020,2226.06)
  BOTTOM w5: v1(1471.57,2760.05) 1656.62,2575 1715,2575 1769.14,2520.86 1769.14,2423.26 v1(1760.87,2414.99) ; v1(2020,2226.06) 2025.43,2220.63 U16.33@2052.48,2220.63
PHY0_LED2/CFG_LDO1: C131.2 J22.12 R175.1 U16.34 | length 2003.9
  TOP w5: v1(1745.02,2388.42) 1776.37,2357.07 1897.68,2357.07 1940,2314.75 1940,2285.86 1975.86,2250 v1(2000,2250) ; J22.12@1875.8,3382.9 1875.8,3273.94 1839,3237.14 1839,3117.43 1986.43,2970 2072.86,2970 2171,2871.86 2171,2787.41 2145.59,2762 2075,2762 2058,2745 2058,2704.72 R175.1@2075,2687.72 C131.2@2035,2687.72 1987.95,2734.77 v1(1974.17,2734.77)
  BOTTOM w5: v1(1745.02,2388.42) 1765.1,2388.42 1790,2413.32 1790,2435 1796.15,2441.15 1796.15,2641.15 1889.77,2734.77 v1(1974.17,2734.77) ; v1(2000,2250) 2021.98,2250 2035.6,2236.38 U16.34@2052.48,2236.38
PHY0_MDI0+: R169.1 U16.1 | length 165.3
  BOTTOM w4: R169.1@2005,2472.28 2018,2459.28 2018,2442.86 2035.43,2425.43 2035.43,2387.57 2048,2375 2072.86,2375 2077.01,2370.85 2077.01,2367.01 2074.13,2364.13 U16.1@2074.13,2352.52
PHY0_MDI0-: R168.1 U16.2 | length 164.9
  BOTTOM w4: R168.1@2040,2472.28 2028,2460.28 2028,2447 2045.43,2429.57 2045.43,2391.72 2052.14,2385 2077,2385 2087.01,2374.99 2087.01,2367.99 2089.88,2365.12 U16.2@2089.88,2352.52
PHY0_MDI1+: R167.1 U16.4 | length 137.2
  BOTTOM w4: R167.1@2085,2472.28 2097.5,2459.78 2097.5,2448.36 2124.26,2421.6 2124.26,2375 2121.38,2372.13 U16.4@2121.38,2352.52
PHY0_MDI1-: R166.1 U16.5 | length 137.2
  BOTTOM w4: R166.1@2120,2472.28 2107.5,2459.78 2107.5,2452.5 2134.26,2425.74 2134.26,2375 2137.13,2372.13 U16.5@2137.13,2352.52
PHY0_MDI2+: R165.1 U16.6 | length 133.1
  BOTTOM w4: U16.6@2152.87,2352.52 2152.87,2372.13 2155.75,2375 2155.75,2434.89 2172.5,2451.64 2172.5,2459.78 R165.1@2160,2472.28
PHY0_MDI2-: R164.1 U16.7 | length 133.1
  BOTTOM w4: U16.7@2168.62,2352.52 2168.62,2371.65 2165.75,2374.53 2165.75,2430.75 2182.5,2447.5 2182.5,2459.78 R164.1@2195,2472.28
PHY0_MDI3+: R163.1 U16.9 | length 162.5
  BOTTOM w4: U16.9@2200.12,2352.52 2200.12,2365.12 2203,2368 2203,2378 2215,2390 2235,2390 2262.5,2417.5 2262.5,2459.78 R163.1@2250,2472.28
PHY0_MDI3-: R162.1 U16.10 | length 162.5
  BOTTOM w4: U16.10@2215.87,2352.52 2215.87,2364.13 2213,2367.01 2213,2373.85 2219.14,2380 2239.14,2380 2272.5,2413.36 2272.5,2459.78 R162.1@2285,2472.28
PHY0_REG_OUT: L31.1 U16.30
PHY0_RXCLK/PHYAD1: R179.2 R192.1 U16.27 | length 138.3
  BOTTOM w5: U16.27@2121.38,2167.48 2121.38,2145.62 2123.13,2143.87 2123.13,2090.87 2130,2084 R179.2@2130,2072.72 R192.1@2170,2072.72
PHY0_XTALIN: C129.2 U16.36 XT3.3 | length 251.3
  BOTTOM w5: XT3.3@1834.57,2232.76 1871.81,2270 1942.72,2270 C129.2@1955,2257.72 1975.61,2278.33 2021.94,2278.33 2032.4,2267.87 U16.36@2052.48,2267.87
PHY0_XTALOUT: C128.2 U16.37 XT3.1 | length 165.1
  BOTTOM w5: XT3.1@1905.43,2327.24 1930.04,2327.24 C128.2@1955,2302.28 1968.95,2288.33 2026.08,2288.33 2030.79,2283.62 U16.37@2052.48,2283.62
PHY2_MDI0+: R145.1 U15.1 | length 165.6
  BOTTOM w4: R145.1@2750,2482.28 2762,2470.28 2762,2454 2801,2415 2840.86,2415 2852.76,2403.1 2852.76,2398.76 2849.88,2395.88 U15.1@2849.88,2383.74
